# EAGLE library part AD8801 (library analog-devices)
ANALOG DEVICES
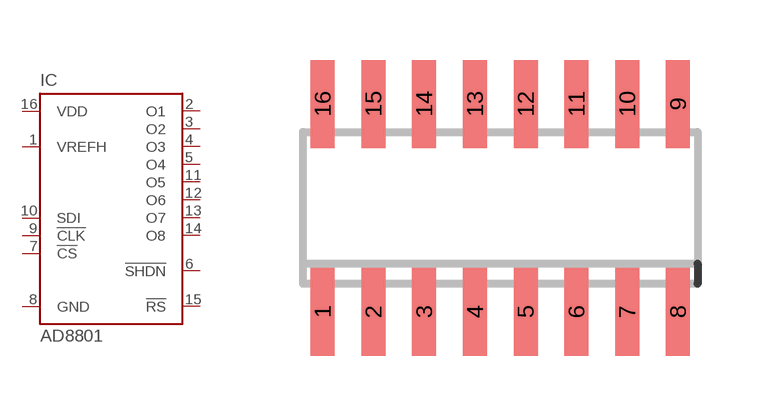
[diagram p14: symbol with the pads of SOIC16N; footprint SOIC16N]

Designator prefix IC

## AD8801 (OC_FARNELL: unknown; OC_NEWARK: unknown)  [SOIC16N]
1  VREFH  in
2  O1  out
3  O2  out
4  O3  out
5  O4  out
6  !SHDN  in
7  !CS  in
8  GND  pwr
9  !CLK  in
10  SDI  in
11  O5  out
12  O6  out
13  O7  out
14  O8  out
15  !RS  in
16  VDD  pwr

## Footprint SOIC16N (pad centres in mm)
SMALL OUTLINE INTEGRATED CIRCUIT
smd 0.6 x 2.2: 1 -4.445,-2.6; 2 -3.175,-2.6; 3 -1.905,-2.6; 4 -0.635,-2.6; 5 0.635,-2.6; 6 1.905,-2.6; 7 3.175,-2.6; 8 4.445,-2.6; 9 4.445,2.6; 10 3.175,2.6; 11 1.905,2.6; 12 0.635,2.6; 13 -0.635,2.6; 14 -1.905,2.6; 15 -3.175,2.6; 16 -4.445,2.6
